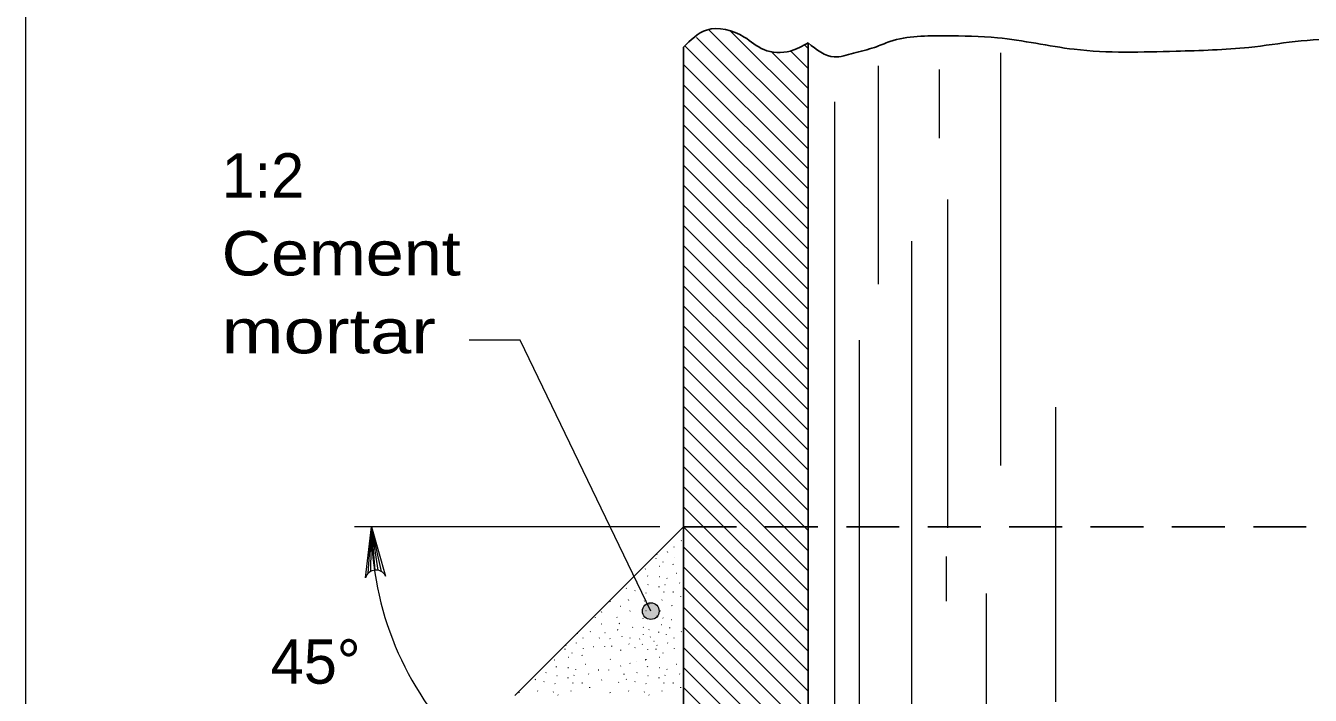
# Model space of a CAD drawing. Extents: x 1302.9 to 1336.9, y 688.5 to 710.5.
# Drawn here: x 1314.494 to 1319.007, y 700.767 to 703.122 of the extents above; entities that cross this region are included whole.
import ezdxf

# ---------------------------------------------------------------- set-up
doc = ezdxf.new("R2010")
doc.units = 0
doc.header["$LTSCALE"] = 0.062
doc.linetypes.add('MEDIUM_DASHED', pattern=[4.5, 3, -1.5])
doc.layers.add('1', color=7, linetype='Continuous', lineweight=13)

msp = doc.modelspace()

# ---------------------------------------------------------------- hatches: boundary and pattern name
at = {"layer": '1'}
msp.add_hatch(color=256, dxfattribs=at).paths.add_polyline_path([(1316.71961, 701.0633, 1), (1316.66061, 701.0633, 1)])

# ---------------------------------------------------------------- linework, layer by layer
for p, q in [((1314.49383, 700.27), (1314.49383, 706.63708)), ((1317.24267, 702.75983), (1316.892, 703.1105)), ((1317.24267, 702.83058), (1316.96867, 703.1045)), ((1317.24267, 702.6185), (1316.81075, 703.05042)), ((1317.24267, 702.68925), (1316.85108, 703.08067)), ((1317.24267, 703.0425), (1317.23008, 703.05517)), ((1317.24267, 702.90117), (1317.11292, 703.03092)), ((1317.24267, 702.97192), (1317.18117, 703.03333)), ((1317.92025, 701.57483), (1317.92025, 703.02675)), ((1317.24267, 702.54783), (1316.80542, 702.98508)), ((1317.48883, 702.98067), (1317.48883, 702.2135)), ((1317.70425, 702.72692), (1317.70425, 702.96808)), ((1317.24267, 702.47717), (1316.80542, 702.91442)), ((1317.24267, 702.4065), (1316.80542, 702.84375)), ((1317.33667, 698.46067), (1317.33667, 702.85392)), ((1317.24267, 702.33583), (1316.80542, 702.77308)), ((1317.24267, 702.26517), (1316.80542, 702.70242)), ((1317.24267, 702.1945), (1316.80542, 702.63175)), ((1317.24267, 702.12383), (1316.80542, 702.56108)), ((1317.73333, 701.35583), (1317.73333, 702.51142)), ((1317.24267, 702.05317), (1316.80542, 702.49042)), ((1317.24267, 701.9825), (1316.80542, 702.41975)), ((1317.24267, 701.91183), (1316.80542, 702.34908)), ((1317.60758, 699.14283), (1317.60758, 702.36408)), ((1317.24267, 701.84117), (1316.80542, 702.27842)), ((1317.24267, 701.7705), (1316.80542, 702.20775)), ((1317.24267, 701.69983), (1316.80542, 702.13708)), ((1317.24267, 701.62917), (1316.80542, 702.06642)), ((1317.42233, 702.01592), (1317.42233, 699.18083)), ((1317.24267, 701.5585), (1316.80542, 701.99575)), ((1317.24267, 701.48783), (1316.80542, 701.92508)), ((1317.24267, 701.41717), (1316.80542, 701.85442)), ((1317.24267, 701.34642), (1316.80542, 701.78367)), ((1318.11208, 701.78092), (1318.11208, 700.74375)), ((1317.24267, 701.27575), (1316.80542, 701.713)), ((1317.24267, 701.20508), (1316.80542, 701.64233)), ((1317.24267, 701.13442), (1316.80542, 701.57167)), ((1317.24267, 701.06375), (1316.80542, 701.501)), ((1317.24267, 700.99308), (1316.80542, 701.43033)), ((1316.72208, 701.36), (1315.64875, 701.36)), ((1315.69725, 701.19642), (1315.70858, 701.36)), ((1315.70708, 701.20333), (1315.70858, 701.36)), ((1315.72117, 701.20742), (1315.70858, 701.36)), ((1315.73258, 701.20667), (1315.70858, 701.36)), ((1315.74408, 701.20217), (1315.70858, 701.36)), ((1317.24267, 700.92242), (1316.80542, 701.35967)), ((1316.74567, 701.29933), (1316.74542, 701.3)), ((1316.77275, 701.28767), (1316.77225, 701.28933)), ((1316.79708, 701.31058), (1316.79792, 701.31142)), ((1317.24267, 700.85175), (1316.80542, 701.289)), ((1316.70917, 701.24808), (1316.70858, 701.24975)), ((1316.71225, 701.26208), (1316.71175, 701.26375)), ((1316.7495, 701.26975), (1316.74892, 701.27142)), ((1316.77308, 701.25142), (1316.77392, 701.25225)), ((1317.72975, 701.09775), (1317.72975, 701.25483)), ((1316.671, 701.21117), (1316.67183, 701.212)), ((1316.72067, 701.22142), (1316.72242, 701.22108)), ((1316.734, 701.23475), (1316.73342, 701.23633)), ((1316.76967, 701.22617), (1316.76917, 701.22783)), ((1316.78042, 701.19667), (1316.78208, 701.19633)), ((1317.24267, 700.78108), (1316.80542, 701.21833)), ((1316.64158, 701.16633), (1316.64242, 701.16717)), ((1316.67925, 701.186), (1316.67867, 701.18767)), ((1316.67983, 701.15608), (1316.68067, 701.15692)), ((1316.71908, 701.18508), (1316.72083, 701.18467)), ((1316.72, 701.1475), (1316.7195, 701.14917)), ((1316.73975, 701.15625), (1316.74058, 701.15708)), ((1316.74717, 701.17742), (1316.74667, 701.17908)), ((1316.79217, 701.16117), (1316.79158, 701.16283)), ((1317.24267, 700.71042), (1316.80542, 701.14767)), ((1316.60317, 701.14333), (1316.60483, 701.14292)), ((1316.61258, 701.10092), (1316.61208, 701.10258)), ((1316.63458, 701.13458), (1316.63542, 701.13542)), ((1316.67233, 701.12792), (1316.674, 701.12708)), ((1316.72883, 701.10217), (1316.72967, 701.103)), ((1316.73708, 701.12883), (1316.73658, 701.1305)), ((1316.768, 701.13092), (1316.76967, 701.13058)), ((1316.79608, 701.11333), (1316.7955, 701.115)), ((1317.86967, 698.91258), (1317.86967, 701.1255)), ((1316.518, 701.05842), (1316.51742, 701.06008)), ((1316.54825, 701.09475), (1316.54767, 701.09642)), ((1316.58375, 701.08075), (1316.5855, 701.08033)), ((1316.61675, 701.0635), (1316.61758, 701.06433)), ((1316.66733, 701.098), (1316.66817, 701.09883)), ((1316.67317, 701.06475), (1316.674, 701.06558)), ((1316.68317, 701.088), (1316.68483, 701.08717)), ((1316.723, 701.06367), (1316.72475, 701.06333)), ((1316.765, 701.08083), (1316.7645, 701.0825)), ((1317.24267, 700.63975), (1316.80542, 701.077)), ((1316.49633, 701.04058), (1316.49575, 701.04225)), ((1316.5155, 701.01883), (1316.51725, 701.01842)), ((1316.5715, 701.04058), (1316.57092, 701.04225)), ((1316.57833, 701.02033), (1316.58008, 701.02)), ((1316.66383, 701.03592), (1316.66317, 701.03758)), ((1316.71383, 701.0455), (1316.71325, 701.04717)), ((1316.72658, 701.0155), (1316.72742, 701.01633)), ((1316.73325, 701.03825), (1316.73267, 701.03992)), ((1316.76258, 701.03425), (1316.76425, 701.03392)), ((1316.42583, 700.97958), (1316.42558, 700.98025)), ((1316.43367, 700.98458), (1316.4295, 700.983)), ((1316.45292, 700.96792), (1316.45242, 700.96958)), ((1316.47725, 700.99075), (1316.47808, 700.99158)), ((1316.50908, 700.96833), (1316.50992, 700.96917)), ((1316.52908, 700.98742), (1316.52992, 700.98833)), ((1316.54575, 700.96667), (1316.54742, 700.96583)), ((1316.57217, 700.99792), (1316.57383, 700.99758)), ((1316.58908, 700.97417), (1316.58992, 700.975)), ((1316.61742, 700.96833), (1316.61825, 700.96917)), ((1316.62658, 701.005), (1316.626, 701.00667)), ((1316.66283, 701.00642), (1316.6645, 701.00608)), ((1316.664, 700.98), (1316.66483, 700.98083)), ((1316.68317, 700.99742), (1316.684, 700.99817)), ((1316.68817, 700.97167), (1316.689, 700.9725)), ((1316.7185, 700.98833), (1316.71792, 700.98992)), ((1316.74567, 700.97958), (1316.74508, 700.98125)), ((1316.75725, 701.00342), (1316.75675, 701.00508)), ((1316.77275, 700.96792), (1316.77225, 700.96958)), ((1316.79708, 700.99075), (1316.79792, 700.99158)), ((1317.24267, 700.56908), (1316.80542, 701.00633)), ((1316.38933, 700.92825), (1316.38875, 700.92992)), ((1316.39242, 700.94225), (1316.39192, 700.94392)), ((1316.42967, 700.94992), (1316.42908, 700.95158)), ((1316.45325, 700.93158), (1316.45408, 700.93242)), ((1316.48758, 700.93875), (1316.48933, 700.93833)), ((1316.52883, 700.93733), (1316.52833, 700.939)), ((1316.55367, 700.93908), (1316.55308, 700.94075)), ((1316.5855, 700.92492), (1316.58492, 700.92658)), ((1316.61417, 700.94683), (1316.61358, 700.9485)), ((1316.63458, 700.93392), (1316.63542, 700.93475)), ((1316.65075, 700.965), (1316.65158, 700.96583)), ((1316.66067, 700.94533), (1316.66008, 700.947)), ((1316.68, 700.928), (1316.67942, 700.92967)), ((1316.7015, 700.95633), (1316.70117, 700.95592)), ((1316.70217, 700.95667), (1316.7015, 700.95633)), ((1316.70917, 700.92825), (1316.70858, 700.92992)), ((1316.71225, 700.94225), (1316.71175, 700.94392)), ((1316.7495, 700.94992), (1316.74892, 700.95158)), ((1316.77308, 700.93158), (1316.77392, 700.93242)), ((1317.24267, 700.49842), (1316.80542, 700.93567)), ((1316.35117, 700.89133), (1316.352, 700.89217)), ((1316.40083, 700.90158), (1316.40258, 700.90125)), ((1316.41417, 700.91492), (1316.41358, 700.9165)), ((1316.44983, 700.90633), (1316.44933, 700.908)), ((1316.46058, 700.87683), (1316.46225, 700.8765)), ((1316.54775, 700.89292), (1316.54858, 700.89375)), ((1316.61725, 700.8785), (1316.61675, 700.88017)), ((1316.64083, 700.88667), (1316.64167, 700.8875)), ((1316.671, 700.89133), (1316.67183, 700.89217)), ((1316.67225, 700.89392), (1316.67242, 700.89217)), ((1316.72067, 700.90158), (1316.72242, 700.90125)), ((1316.734, 700.91492), (1316.73342, 700.9165)), ((1316.78042, 700.87683), (1316.78208, 700.8765)), ((1316.32167, 700.8465), (1316.3225, 700.84733)), ((1316.35942, 700.86617), (1316.35883, 700.86783)), ((1316.36, 700.83633), (1316.36083, 700.83717)), ((1316.39925, 700.86525), (1316.401, 700.86483)), ((1316.41992, 700.8365), (1316.42075, 700.83733)), ((1316.42733, 700.85758), (1316.42683, 700.85925)), ((1316.47233, 700.84133), (1316.47175, 700.84308)), ((1316.50542, 700.85675), (1316.50717, 700.85633)), ((1316.54283, 700.85533), (1316.54225, 700.857)), ((1316.58425, 700.86967), (1316.58508, 700.8705)), ((1316.59708, 700.84067), (1316.59658, 700.84225)), ((1316.64158, 700.8465), (1316.64242, 700.84733)), ((1316.67925, 700.86617), (1316.67867, 700.86783)), ((1316.67983, 700.83633), (1316.68067, 700.83717)), ((1316.71908, 700.86525), (1316.72083, 700.86483)), ((1316.73975, 700.8365), (1316.74058, 700.83733)), ((1316.74717, 700.85758), (1316.74667, 700.85925)), ((1316.79217, 700.84133), (1316.79158, 700.84308)), ((1317.24267, 700.42775), (1316.80542, 700.865)), ((1316.28333, 700.82358), (1316.285, 700.82317)), ((1316.31467, 700.81483), (1316.3155, 700.81567)), ((1316.3525, 700.80808), (1316.35417, 700.80725)), ((1316.40017, 700.82775), (1316.39967, 700.82942)), ((1316.41725, 700.809), (1316.41675, 700.81067)), ((1316.44817, 700.81117), (1316.44983, 700.81083)), ((1316.47625, 700.7935), (1316.47567, 700.79517)), ((1316.51675, 700.82025), (1316.51758, 700.82108)), ((1316.5765, 700.8125), (1316.57733, 700.81333)), ((1316.60317, 700.82358), (1316.60483, 700.82317)), ((1316.63458, 700.81483), (1316.63542, 700.81567)), ((1316.67233, 700.80808), (1316.674, 700.80725)), ((1316.72, 700.82775), (1316.7195, 700.82942)), ((1316.73708, 700.809), (1316.73658, 700.81067)), ((1316.768, 700.81117), (1316.76967, 700.81083)), ((1316.79608, 700.7935), (1316.7955, 700.79517)), ((1317.24267, 700.35708), (1316.80542, 700.79433)), ((1316.22842, 700.77492), (1316.22783, 700.77658)), ((1316.29275, 700.78108), (1316.29225, 700.78275)), ((1316.3475, 700.77817), (1316.34833, 700.779)), ((1316.36333, 700.76817), (1316.365, 700.76733)), ((1316.409, 700.78233), (1316.40983, 700.78317)), ((1316.54825, 700.77492), (1316.54767, 700.77658)), ((1316.61258, 700.78108), (1316.61208, 700.78275)), ((1316.66733, 700.77817), (1316.66817, 700.779)), ((1316.68317, 700.76817), (1316.68483, 700.76733)), ((1316.72883, 700.78233), (1316.72967, 700.78317))]:
    msp.add_line(p, q, dxfattribs=at)
at = {"layer": '1', "lineweight": 25}
for p, q in [((1316.80542, 700.04825), (1316.80542, 703.0465)), ((1316.80542, 701.36), (1316.21192, 700.76658))]:
    msp.add_line(p, q, dxfattribs=at)
at = {"layer": '1', "linetype": 'MEDIUM_DASHED', "lineweight": 25}
msp.add_line((1316.80542, 701.36), (1322.08425, 701.36), dxfattribs=at)
at = {"layer": '1', "lineweight": 25}
msp.add_lwpolyline([(1317.24267, 703.06167), (1317.24267, 700.04825), (1316.80542, 700.04825)], dxfattribs=at)
at = {"layer": '1'}
for points in [[(1316.69008, 701.06333), (1316.23175, 702.01658), (1316.05233, 702.01658)], [(1315.68783, 701.18075), (1315.70858, 701.36), (1315.75842, 701.1865)]]:
    msp.add_lwpolyline(points, dxfattribs=at)
msp.add_circle((1316.69011, 701.0633), 0.0295, dxfattribs=at)
for centre, radius, start, end in [((1316.80539, 701.35999), 1.09683, 179.99836, 224.99685), ((1315.72436, 701.16938), 0.0382, 26.81238, 162.63851)]:
    msp.add_arc(centre, radius, start, end, dxfattribs=at)
at = {"layer": '1', "lineweight": 25}
for points in [[(1316.80542, 703.0465), (1316.88608, 703.10683), (1317.0185, 703.08225), (1317.08725, 703.038), (1317.1805, 703.03308), (1317.24267, 703.0615)], [(1321.64692, 703.06167), (1321.55125, 703.09325), (1321.38258, 703.1), (1321.17342, 703.07975), (1320.81592, 703.03917), (1320.44483, 703.0595), (1320.15475, 703.07975), (1319.85783, 703.0595), (1319.57458, 703.05267), (1319.29125, 703.073), (1318.95392, 703.06625), (1318.79192, 703.04592), (1318.53558, 703.03242), (1318.17808, 703.03917), (1317.90817, 703.07975), (1317.726, 703.0865), (1317.53042, 703.06625), (1317.47642, 703.04592), (1317.40217, 703.02567), (1317.33475, 703.01225), (1317.24267, 703.0615)]]:
    msp.add_spline(points, degree=3, dxfattribs=at)

# ---------------------------------------------------------------- texts
at = {"layer": '1'}
for s, p in [('1:2', (1315.18233, 702.51767)), ('45°', (1315.355, 700.80783))]:
    msp.add_text(s, height=0.156, dxfattribs=at).set_placement(p)
for s, width, p in [('Cement', 1.15, (1315.18233, 702.24367)), ('mortar', 1.25, (1315.18233, 701.96967))]:
    msp.add_text(s, height=0.156, dxfattribs=dict(at, width=width)).set_placement(p)

doc.saveas('drawing.dxf')
